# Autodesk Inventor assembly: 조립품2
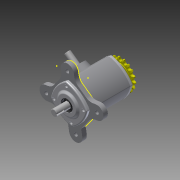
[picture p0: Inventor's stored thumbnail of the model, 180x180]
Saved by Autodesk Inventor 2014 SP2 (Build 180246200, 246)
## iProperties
Created: 2016-05
Part Number: 조립품2
Document SubType Name: Assembly
Designer: apexhp001
Author: apexhp001
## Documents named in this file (11)
- C:\Users\apexhp001\Desktop\460508V1011\조립품2.iam
- C:\Users\apexhp001\Desktop\460508V1011\본체.ipt
- C:\Users\apexhp001\Desktop\460508V1011\M4x0.7x12.ipt
- C:\Users\apexhp001\Desktop\460508V1011\베어링-6203.ipt
- C:\Users\apexhp001\Desktop\460508V1011\부시.ipt
- C:\Users\apexhp001\Desktop\460508V1011\스프로킷.ipt
- C:\Users\apexhp001\Desktop\460508V1011\슬라이더.ipt
- C:\Users\apexhp001\Desktop\460508V1011\오일실.ipt
- C:\Users\apexhp001\Desktop\460508V1011\커버.ipt
- C:\Users\apexhp001\Desktop\460508V1011\키5x5.ipt
- C:\Users\apexhp001\Desktop\460508V1011\편심축.ipt
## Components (4 placed, 1 different names)
1. M4x0.7x12:1
2. M4x0.7x12:2
3. M4x0.7x12:3
4. M4x0.7x12:4
